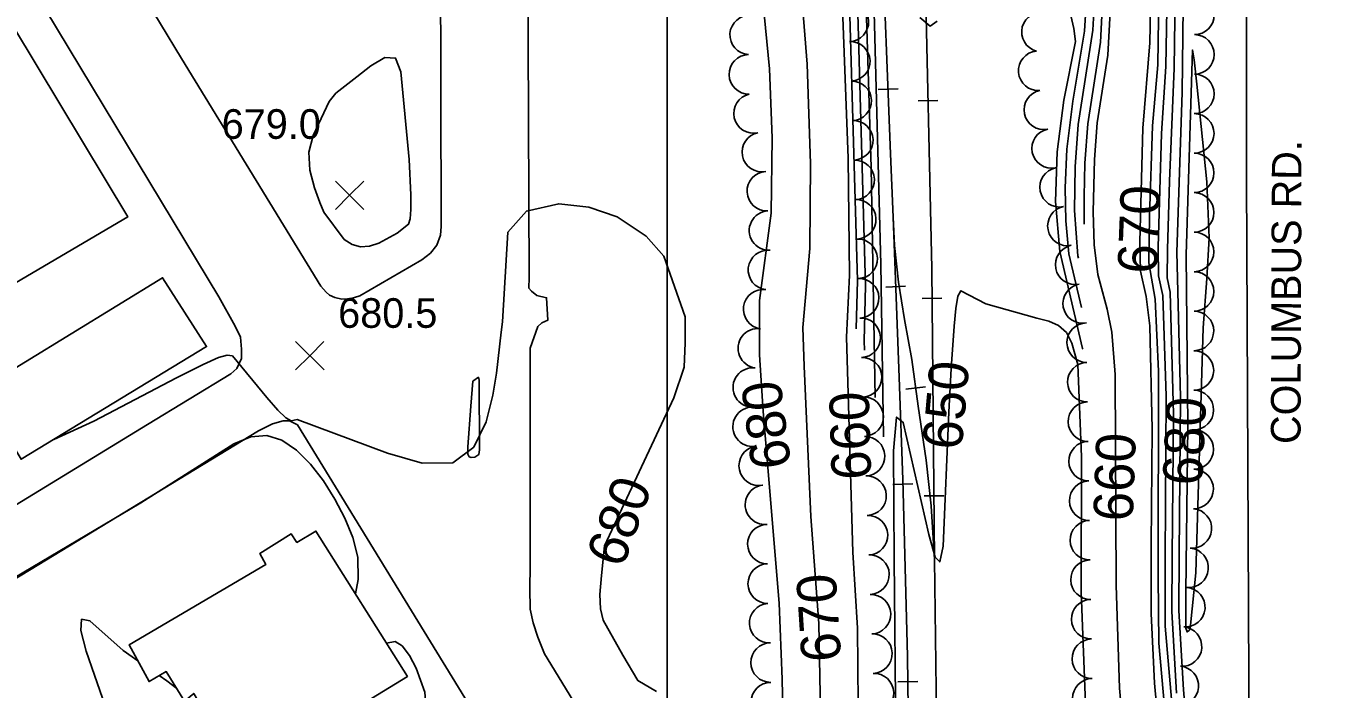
# Model space of a CAD drawing. Extents: x 79600 to 91800, y 75600 to 84400.
# Drawn here: x 83676 to 84333, y 83212 to 83548 of the extents above; entities that cross this region are included whole.
import ezdxf

# ---------------------------------------------------------------- set-up
doc = ezdxf.new("R2010")
doc.units = 0
for name, color, linetype in [('084-085$0$BLDG', 7, 'Continuous'), ('084-085$0$GRID', 7, 'Continuous'), ('084-085$0$INDEX', 7, 'Continuous'), ('084-085$0$INDXLBL', 7, 'Continuous'), ('084-085$0$INTER', 7, 'Continuous'), ('084-085$0$ROAD', 7, 'Continuous'), ('084-085$0$ROAD-NAME', 7, 'Continuous'), ('084-085$0$RR', 7, 'Continuous'), ('084-085$0$SPOTMARK', 7, 'Continuous'), ('084-085$0$SPOTS', 7, 'Continuous'), ('084-085$0$TREES', 7, 'Continuous')]:
    doc.layers.add(name, color=color, linetype=linetype)

# ---------------------------------------------------------------- blocks, each defined once
blk = doc.blocks.new('084-085$0$RRTICK100')
blk.add_line((0, -5), (0, 5))
blk = doc.blocks.new('084-085$0$SPOTX')
at = {"layer": '084-085$0$SPOTMARK'}
for p, q in [((-0.37, 0.358), (0.351, -0.358)), ((-0.012, 0), (0.347, 0.358)), ((-0.012, 0), (-0.37, -0.358))]:
    blk.add_line(p, q, dxfattribs=at)

msp = doc.modelspace()

# ---------------------------------------------------------------- linework, layer by layer
at = {"layer": '084-085$0$BLDG'}
for points in [[(83656.05, 83409.27), (83726.99, 83450.92), (83634.6, 83604.41), (83580.09, 83570.02), (83590.15, 83553.45), (83572.33, 83543.07), (83584.43, 83523.56), (83564.76, 83510.69), (83586.14, 83474.44), (83611.09, 83486.73), (83630.9, 83451.56), (83623.46, 83447.62), (83631.34, 83431.82), (83639.71, 83436.38)], [(83651.98, 83363.38), (83673.04, 83328.22), (83766.9, 83385.25), (83744.6, 83420.09)], [(83790.49, 83170.53), (83868.55, 83218.29), (83822.21, 83291.85), (83812.61, 83286.19), (83809.63, 83290.52), (83793.84, 83280.47), (83796.82, 83274.9), (83727.74, 83234.35), (83737.81, 83215.75), (83746.48, 83220.78), (83755.75, 83205.76), (83760.39, 83209.68), (83766.05, 83199.92), (83771.47, 83202.59)]]:
    msp.add_lwpolyline(points, close=True, dxfattribs=at)
at = {"layer": '084-085$0$GRID'}
msp.add_line((84000, 84000), (84000, 80000), dxfattribs=at)
at = {"layer": '084-085$0$INDEX'}
for points in [[(84098.21, 83004.57), (84097.9, 83016.04), (84093.6, 83032.04), (84087.44, 83045.47), (84084.8, 83054.06), (84081.25, 83079.9), (84078.78, 83112.73), (84077.48, 83209.4), (84076.75, 83245.14), (84072.74, 83299.35), (84069.3, 83375.33), (84068.57, 83395), (84072.12, 83434.9), (84072.45, 83477.97), (84070.87, 83528.2), (84067.89, 83566.48), (84062.26, 83748.94), (84061.54, 83787.82), (84063.03, 83843.29), (84063.12, 83883.79), (84061.23, 83929.16)], [(84103.44, 82982.83), (84105.56, 83008.99), (84104.28, 83030.59), (84101.98, 83057.1), (84098.91, 83079.11), (84096.87, 83100.01), (84096.86, 83185.12), (84096.3, 83242.79), (84093.96, 83281.21), (84090.74, 83389.97), (84092.25, 83421.43), (84091.62, 83480.68), (84087.15, 83596.78), (84083.16, 83764.7), (84083.3, 83845.36), (84082.27, 83908.69), (84081.18, 83929.35)], [(84245.47, 83600.18), (84244.28, 83538.94), (84240.76, 83495.75), (84239.16, 83438.3), (84239.52, 83423.36), (84242.4, 83410.6), (84244.22, 83395.72), (84245.5, 83343.54), (84244.97, 83284.69), (84244.92, 83250.19), (84246.56, 83214.98), (84257.02, 83101.83)], [(84059.72, 83144.6), (84058.11, 83216.88), (84056.7, 83255.45), (84048.63, 83352.37), (84046.79, 83381.08), (84046.79, 83408.54), (84052.7, 83452.72), (84053.15, 83490.9), (84051.82, 83525.78), (84047.27, 83572.74)], [(84224.98, 83570.21), (84223.02, 83532.8), (84217.54, 83498.5), (84216.21, 83479.95), (84215.64, 83453.43), (84216.14, 83436.69), (84218, 83421.81), (84222.59, 83404.28), (84225.11, 83392.64), (84226.77, 83371.07), (84227.15, 83264.58), (84228.88, 83212.3), (84244.18, 83039.31)], [(83689.63, 83338.3), (83709.89, 83347.57), (83751.71, 83369.43), (83765.1, 83376.22), (83772.95, 83379.72), (83777.3, 83380.92), (83780.02, 83380.56), (83797.35, 83359.48), (83802.98, 83353.01), (83807.05, 83349.2), (83809.67, 83347.63), (83812.82, 83348.38), (83858.42, 83331.35), (83876.03, 83326.27), (83891.49, 83326.41), (83902.09, 83334.35), (83908.4, 83347.21), (83911.8, 83360.74), (83913.59, 83371.81), (83915.93, 83392.64), (83916.61, 83397.81), (83919.37, 83443.23), (83928.79, 83453.87), (83945.17, 83457.55), (83960.31, 83455.91), (83974.64, 83451), (83989.38, 83441.18), (83998.39, 83430.95), (84009.03, 83400.26), (84009.03, 83387.16), (84008.62, 83374.88), (84003.3, 83359.33), (83968.36, 83284.37), (83966.71, 83269.48), (83965.91, 83259.85), (83966.19, 83252.55), (83967.62, 83246.8), (83977.53, 83229.16), (83985.08, 83216.19), (83994.63, 83210.69)], [(84115.78, 83189.02), (84114.89, 83277.88), (84114.62, 83332.47), (84116.12, 83349.61), (84119.47, 83346.92), (84132.47, 83290.14), (84135.55, 83278.66), (84137.9, 83276.3), (84139.59, 83284.19), (84142.59, 83352.12), (84143.74, 83374.19), (84145.18, 83395.56), (84146.04, 83404.55), (84147.15, 83410.82), (84148.65, 83413.56), (84161.26, 83406.99), (84187.08, 83399.73), (84193.09, 83398.2), (84198.11, 83395.97), (84202.04, 83392.34), (84204.84, 83386.98), (84207.78, 83376.13), (84209.68, 83329.45), (84209.45, 83261.09), (84211.82, 83200.04)], [(83842.25, 83260.05), (83843.59, 83267.43), (83843.46, 83278.61), (83840.97, 83288.7), (83836.88, 83298.34), (83831.82, 83307.98), (83826.01, 83317.29), (83819.53, 83325.75), (83812.49, 83332.81), (83805.04, 83337.85), (83797.33, 83340.25), (83789.38, 83339.56), (83780.69, 83336.08), (83733.67, 83306.11), (83623.29, 83240.82)], [(83717.01, 83199.51), (83710.15, 83219.01), (83705.95, 83231.12), (83703.28, 83241.53), (83703.65, 83247.29), (83707.89, 83246.49), (83724.62, 83231.44), (83732.14, 83226.22)], [(83899.33, 83144.7), (83888.9, 83162.76), (83876.24, 83184.65), (83872.84, 83190.38), (83871.65, 83194.15), (83876.74, 83202.7), (83877.7, 83206.11), (83877.38, 83210.38), (83873.01, 83222.42), (83869.53, 83228.95), (83865.87, 83233.88), (83862.39, 83236.05), (83857.91, 83235.18)], [(83742.93, 83218.72), (83746.76, 83216.06), (83751.81, 83212.15)]]:
    msp.add_lwpolyline(points, dxfattribs=at)
for points in [[(83824.27, 83458.22), (83821.51, 83465.61), (83819.14, 83474.54), (83818.61, 83483.74), (83820.83, 83492.09), (83828.9, 83509.34), (83832.32, 83513.54), (83842.87, 83521.74), (83850.09, 83527.45), (83857.16, 83531.64), (83862.55, 83531.26), (83865.22, 83524.4), (83869.45, 83479.92), (83870.33, 83462.11), (83870.27, 83454.59), (83869.97, 83449.91), (83869.03, 83447.23), (83863.42, 83442.71), (83854, 83437.67), (83849.29, 83436.13), (83844.82, 83435.76), (83840.55, 83436.86), (83836.48, 83439.54), (83826.31, 83453.22)], [(84264.68, 83242.57), (84267.47, 83270.77), (84271.32, 83394.8), (84273.1, 83419.81), (84274.29, 83440.29), (84273.03, 83468.65), (84268.03, 83518.11), (84266.76, 83530.43), (84265.85, 83535.39), (84262.58, 83431.68), (84263.55, 83345.23), (84262.5, 83260.98), (84262.41, 83246.88), (84262.56, 83242.76), (84263.07, 83240.84), (84264.13, 83241.49)]]:
    msp.add_lwpolyline(points, close=True, dxfattribs=at)
at = {"layer": '084-085$0$INTER'}
for points in [[(84095.58, 83394.22), (84096.28, 83418.74), (84090.44, 83623.06), (84087.34, 83768.53), (84087.3, 83844.36), (84086.16, 83911.34), (84085.12, 83929.38)], [(84099.81, 83383.53), (84099.7, 83388.13), (84100.31, 83416.05), (84094.47, 83626.1), (84091.3, 83837.56), (84089.84, 83924.6), (84089.52, 83929.42)], [(84261.5, 83668.47), (84261.83, 83615.02), (84260.69, 83513.84), (84257.9, 83433), (84259.74, 83359.67), (84259.08, 83279.8), (84258.94, 83251.62), (84261.3, 83211.55), (84263.6, 83184.5), (84265.48, 83164.53), (84266.55, 83153.59), (84268.32, 83143.59), (84270.66, 83139.09), (84274.36, 83136.6), (84287.66, 83136.15), (84291.15, 83136.1), (84293.98, 83135.15), (84299.89, 83124.95), (84301.12, 83122.03), (84302.95, 83120.06), (84325.83, 83117.64), (84329.21, 83117.97), (84335.16, 83121.78)], [(84252.74, 83645.15), (84253.63, 83604.06), (84252.44, 83526.98), (84250.19, 83493.05), (84248.53, 83435.65), (84248.58, 83421.14), (84250.77, 83411.09), (84252.47, 83360.21), (84252, 83278.25), (84252.04, 83243.69), (84264.52, 83099.7), (84270.46, 83011.87), (84270.87, 83004.39), (84271.19, 83002.6), (84272.49, 83001.51), (84287.02, 83008.54), (84291.74, 83010.41), (84295.04, 83010.68), (84300.2, 83007.74), (84325.78, 83005.85), (84330.9, 83004.73), (84340.11, 83000.42)], [(84105.21, 83359.47), (84103.18, 83475.89), (84098.38, 83633.3)], [(84249.43, 83609.53), (84248.24, 83527.81), (84245.58, 83497.07), (84244.15, 83451.15), (84243.81, 83427.63), (84246.94, 83409.31), (84248.57, 83372.75), (84248.4, 83268.77), (84248.88, 83235.23), (84260.77, 83100.76)], [(84257.69, 83613.19), (84256.65, 83526.15), (84254.23, 83469), (84253.21, 83434.33), (84253.1, 83420.03), (84254.59, 83412.87), (84256.27, 83351.13), (84255.54, 83279.03), (84255.43, 83251.26), (84257.8, 83209.89)], [(84109.55, 83339.65), (84108.05, 83427.04), (84103.35, 83605.6)], [(84221.19, 83576.55), (84219.24, 83539.41), (84212.81, 83498.06), (84211.36, 83478.08), (84210.97, 83461.26), (84211.04, 83447.19)], [(84213.12, 83575.46), (84211.24, 83544.92), (84205.26, 83509.5), (84202.18, 83485.13), (84201.45, 83465.67), (84201.67, 83448.91), (84203.31, 83432.24), (84209.73, 83405.02)], [(84217.15, 83576), (84215.39, 83545.35), (84208.07, 83497.62), (84206.51, 83476.21), (84206.14, 83454.19), (84207.84, 83431.13), (84208.08, 83430.08)], [(84127.92, 83551.84), (84133.14, 83547.45), (84136.59, 83550.04)], [(84204.23, 83552.89), (84205.72, 83546.28), (84206.72, 83539.77), (84200.67, 83509.97), (84197.36, 83483.8), (84196.55, 83458.68), (84198.79, 83433.35), (84210.23, 83384.33), (84210.31, 83383.88)]]:
    msp.add_lwpolyline(points, dxfattribs=at)
at = {"layer": '084-085$0$ROAD'}
for points in [[(83647.79, 83706.65), (83754.16, 83531.01), (83824.7, 83415.93), (83827.36, 83412.84), (83829.08, 83411.3), (83831.88, 83410.07), (83835.31, 83409.32), (83839.51, 83409.5), (83844.47, 83410.93), (83875.76, 83429.16), (83880.25, 83432.61), (83883.49, 83436.67), (83885.32, 83441.66), (83885.61, 83446.02), (83884.34, 83991.42), (83883.36, 83998.88), (83882.81, 84000)], [(84068.32, 83940.14), (84276.69, 83941.07), (84281.64, 83939.73), (84285.05, 83938.06), (84288.78, 83935.48), (84290.2, 83933.17), (84291.63, 83928.56), (84293.37, 83659.17), (84293.22, 83470.82), (84294.55, 83180.43), (84293.92, 83010.13), (84294.06, 82855.13), (84293.55, 82734.55)], [(83575.91, 83247.54), (83736.98, 83345.88), (83779.11, 83371.49), (83782.2, 83374.15), (83784.5, 83379.3), (83784.63, 83383.96), (83784.12, 83390.02), (83781.45, 83395.6), (83773.11, 83410.48), (83516.22, 83836.1)], [(84218.05, 82779.24), (84095.43, 82965.45), (84054.25, 83035.07), (83974.58, 83169.83), (83937.97, 83229.77), (83934.5, 83238.14), (83932.12, 83245.43), (83930.68, 83252.42), (83930.45, 83262.99), (83930.7, 83273.88), (83930.62, 83384.42), (83934.59, 83395.48), (83936.6, 83397.21), (83939.55, 83398.62), (83939.01, 83409.97), (83934.03, 83411.18), (83931.37, 83413.34), (83929.96, 83414.89), (83930.08, 83420.18), (83928.84, 83739.98)], [(84207.45, 82681.02), (84088.92, 82889.89), (83961.78, 83102.89), (83812.86, 83345.74), (83808.8, 83347.73), (83805.69, 83347.72), (83800.26, 83346.13), (83793.13, 83342.66), (83589.31, 83218.7), (83585.91, 83214.64), (83584.54, 83211.05), (83584.57, 83205.15), (83587.1, 83198.32), (83865.97, 82740.49)]]:
    msp.add_lwpolyline(points, dxfattribs=at)
msp.add_lwpolyline([(83900.64, 83355.16), (83899.06, 83334.47), (83899.08, 83332.29), (83899.09, 83330.74), (83899.87, 83329.5), (83900.81, 83329.19), (83902.67, 83329.36), (83904.68, 83330.62), (83904.98, 83332.95), (83904.91, 83368.24), (83904.44, 83369.79), (83901.65, 83367.76)], close=True, dxfattribs=at)
at = {"layer": '084-085$0$RR'}
for points in [[(84096.53, 83929.49), (84103.19, 83750.54), (84108.53, 83600.06), (84113.09, 83482.78), (84114.33, 83450.83), (84117.45, 83369.65), (84119.19, 83317.95), (84120.62, 83267.02), (84121.62, 83228.43), (84122.17, 83188.76), (84122.4, 83133.8), (84122.52, 83090.42), (84121.47, 83040.54), (84118.06, 82958.59)], [(84117.71, 83929.69), (84124.23, 83761.25), (84130.47, 83582.53), (84133.89, 83424.78), (84135.34, 83277.51), (84136.15, 83211.75), (84136.85, 83140.89), (84137.26, 83098.9), (84137.72, 83052.9), (84137.27, 83003.95), (84137.1, 82959.33), (84135.25, 82930.06)], [(84114.33, 83450.83), (84115.09, 83436.48), (84117.13, 83417.82), (84120.09, 83399.01), (84123.84, 83378.67), (84127.01, 83355.08), (84130.99, 83327.79), (84133.68, 83304.66), (84135.34, 83277.51)]]:
    msp.add_lwpolyline(points, dxfattribs=at)
at = {"layer": '084-085$0$TREES'}
for centre, start, end in [((84266.85, 83553.18), 269.91032, 89.91032), ((84091.94, 83549.62), 272.13965, 92.13965), ((84041.77, 83543.03), 86.28105, 266.28105), ((84189.4, 83544.53), 75.5029, 255.5029), ((84092.68, 83529.63), 272.13965, 92.13965), ((84266.82, 83533.18), 269.91032, 89.91032), ((84041.32, 83523.05), 91.17138, 271.17138), ((84187.76, 83524.89), 94.95486, 274.95486), ((84093.43, 83509.65), 272.13965, 92.13965), ((84266.79, 83513.18), 269.91032, 89.91032), ((84043.71, 83503.3), 102.64422, 282.64422), ((84190.61, 83505.12), 101.45927, 281.45927), ((84094.18, 83489.66), 272.13965, 92.13965), ((84266.76, 83493.18), 269.91032, 89.91032), ((84047.89, 83483.74), 101.46886, 281.46886), ((84194.58, 83485.52), 101.45927, 281.45927), ((84094.92, 83469.67), 272.13965, 92.13965), ((84266.73, 83473.18), 269.91032, 89.91032), ((84050.43, 83463.95), 93.16712, 273.16712), ((84198.56, 83465.92), 101.45438, 281.45438), ((84095.67, 83449.69), 272.13965, 92.13965), ((84266.69, 83453.18), 269.91032, 89.91032), ((84051.53, 83443.99), 93.13155, 273.13155), ((84202.53, 83446.32), 101.45438, 281.45438), ((84096.42, 83429.7), 272.13965, 92.13965), ((84266.66, 83433.18), 269.91032, 89.91032), ((84051.01, 83424.06), 83.86542, 263.86542), ((84206.47, 83426.71), 101.26713, 281.26713), ((84097.16, 83409.72), 272.13965, 92.13965), ((84266.63, 83413.18), 269.91032, 89.91032), ((84048.55, 83404.21), 82.01493, 262.01493), ((84210.28, 83407.08), 100.68636, 280.68636), ((84097.91, 83389.73), 272.13965, 92.13965), ((84266.6, 83393.18), 269.91032, 89.91032), ((84045.85, 83384.39), 82.4669, 262.4669), ((84212.29, 83387.25), 90.92598, 270.92598), ((84098.66, 83369.74), 272.13965, 92.13965), ((84266.57, 83373.18), 269.91032, 89.91032), ((84043.33, 83364.55), 83.0444, 263.0444), ((84212.62, 83367.25), 90.92598, 270.92598), ((84099.41, 83349.76), 272.13965, 92.13965), ((84266.54, 83353.18), 269.91032, 89.91032), ((84043.23, 83344.69), 96.38384, 276.38384), ((84212.94, 83347.26), 90.92598, 270.92598), ((84100.15, 83329.77), 272.13965, 92.13965), ((84266.51, 83333.18), 269.91032, 89.91032), ((84046.33, 83324.95), 101.4934, 281.4934), ((84213.26, 83327.26), 90.92598, 270.92598), ((84100.9, 83309.79), 272.13965, 92.13965), ((84266.43, 83313.18), 269.65487, 89.65487), ((84049.47, 83305.22), 96.54122, 276.54122), ((84213.59, 83307.26), 90.92598, 270.92598), ((84265.54, 83293.22), 265.23882, 85.23882), ((84050.7, 83285.28), 90.54275, 270.54275), ((84101.65, 83289.8), 272.13965, 92.13965), ((84213.91, 83287.26), 90.92598, 270.92598), ((84263.88, 83273.29), 265.23882, 85.23882), ((84050.89, 83265.28), 90.51856, 270.51856), ((84102.39, 83269.81), 272.13965, 92.13965), ((84214.23, 83267.27), 90.92598, 270.92598), ((84262.22, 83253.36), 265.23882, 85.23882), ((84051.63, 83245.31), 93.74672, 273.74672), ((84103.14, 83249.83), 272.13965, 92.13965), ((84214.56, 83247.27), 90.92598, 270.92598), ((84260.56, 83233.43), 265.23882, 85.23882), ((84052.34, 83225.33), 90.30917, 270.30917), ((84103.89, 83229.84), 272.13965, 92.13965), ((84214.88, 83227.27), 90.92598, 270.92598), ((84258.9, 83213.5), 265.23882, 85.23882), ((84052.44, 83205.33), 90.29545, 270.29545), ((84104.63, 83209.86), 272.13965, 92.13965), ((84215.2, 83207.27), 90.92598, 270.92598)]:
    msp.add_arc(centre, 10, start, end, dxfattribs=at)

# ---------------------------------------------------------------- block references
at = {"layer": '084-085$0$RR'}
for p, rotation in [((84111.82, 83515.52), -87.77550837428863), ((84132.05, 83509.68), -88.76092575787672), ((84115.68, 83415.59), -87.80032938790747), ((84134.04, 83409.7), -89.43356168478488), ((84125.77, 83364.3), -82.35365771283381), ((84119.26, 83315.66), -88.39178044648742), ((84135.02, 83309.7), -89.43356168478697), ((84121.8, 83215.69), -89.21005229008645)]:
    msp.add_blockref('084-085$0$RRTICK100', p, dxfattribs=dict(at, rotation=rotation))
at = {"layer": '084-085$0$SPOTS', "xscale": 20, "yscale": 20}
for p in [(83839.55, 83461.89), (83819.37, 83380.62)]:
    msp.add_blockref('084-085$0$SPOTX', p, dxfattribs=at)

# ---------------------------------------------------------------- texts
at = {"layer": '084-085$0$INDXLBL'}
for s, rotation, p in [('670', 87.79653, (84247.88, 83421.93)), ('650', 84.95557, (84149.02, 83332.57)), ('680', 97.1278, (84062.77, 83324.61)), ('660', 91.68535, (84103.29, 83318.12)), ('680', 87.2062, (84270.66, 83314.68)), ('660', 87.91661, (84235.6, 83296.57)), ('680', 70.10754, (83977.42, 83272.55)), ('670', 93.73287, (84088.11, 83226.36))]:
    msp.add_text(s, height=20, rotation=rotation, dxfattribs=at).set_placement(p)
at = {"layer": '084-085$0$ROAD-NAME'}
msp.add_text('COLUMBUS RD.', height=15, rotation=89.79539, dxfattribs=at).set_placement((84320.51, 83335.93))
at = {"layer": '084-085$0$SPOTS'}
for s, p in [('679.0', (83774.55, 83490.42)), ('680.5', (83833.51, 83394.76))]:
    msp.add_text(s, height=15, dxfattribs=at).set_placement(p)

doc.saveas('drawing.dxf')
